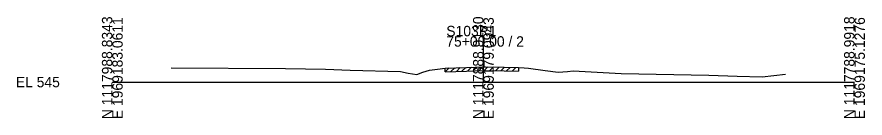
# Model space of a CAD drawing. Extents: x -26 to 203, y -10 to 12018.
# Drawn here: x -25.7 to 202.8, y 11490.3 to 11517.5 of the extents above; entities that cross this region are included whole.
import ezdxf

# ---------------------------------------------------------------- set-up
doc = ezdxf.new("R2010")
doc.units = 0
for name, color, linetype in [('Level 60', 7, 'Continuous'), ('Level 61', 7, 'Continuous'), ('Level 63', 7, 'Continuous')]:
    doc.layers.add(name, color=color, linetype=linetype)

msp = doc.modelspace()

# ---------------------------------------------------------------- linework, layer by layer
at = {"layer": 'Level 60'}
for p, q in [((15.83, 11503.81), (46.63, 11503.65)), ((46.63, 11503.65), (57.42, 11503.46)), ((57.42, 11503.46), (64.1, 11503.25)), ((64.1, 11503.25), (77.7, 11502.83)), ((77.7, 11502.83), (79.76, 11502.44)), ((79.76, 11502.44), (82.07, 11502.06)), ((82.07, 11502.06), (83.67, 11502.63)), ((83.67, 11502.63), (85.46, 11503.2)), ((85.46, 11503.2), (87.61, 11503.5)), ((87.61, 11503.5), (89.73, 11503.78)), ((89.73, 11503.78), (95.43, 11503.96)), ((95.43, 11503.96), (100, 11504.1)), ((100, 11504.1), (100.6, 11504.12)), ((100.6, 11504.12), (105.57, 11504)), ((105.57, 11504), (109.48, 11503.93)), ((109.48, 11503.93), (110.99, 11503.8)), ((110.99, 11503.8), (112.15, 11503.72)), ((112.15, 11503.72), (116.64, 11503.13)), ((116.64, 11503.13), (120.12, 11502.66)), ((120.12, 11502.66), (122.64, 11502.84)), ((122.64, 11502.84), (124.18, 11503)), ((124.18, 11503), (137.1, 11502.34)), ((137.1, 11502.34), (160.73, 11501.84)), ((175.09, 11501.43), (181.41, 11502.12)), ((160.73, 11501.84), (168.37, 11501.6)), ((168.37, 11501.6), (175.09, 11501.43))]:
    msp.add_line(p, q, dxfattribs=at)
at = {"layer": 'Level 61'}
for p, q in [((89.73, 11502.78), (90.77, 11503.81)), ((89.73, 11502.78), (89.73, 11503.78)), ((89.73, 11502.78), (95.43, 11502.96)), ((91.23, 11502.83), (92.27, 11503.86)), ((92.73, 11502.87), (93.77, 11503.91)), ((94.23, 11502.92), (95.27, 11503.95)), ((95.43, 11502.96), (100, 11503.1)), ((95.73, 11502.97), (96.77, 11504)), ((97.23, 11503.01), (98.27, 11504.04)), ((98.73, 11503.06), (99.77, 11504.09)), ((100, 11503.1), (100.6, 11503.12)), ((100.23, 11503.11), (101.23, 11504.1)), ((100.6, 11503.12), (105.57, 11503)), ((101.73, 11503.09), (102.71, 11504.07)), ((103.23, 11503.06), (104.21, 11504.03)), ((104.73, 11503.02), (105.71, 11504)), ((105.57, 11503), (109.48, 11502.93)), ((106.23, 11502.99), (107.22, 11503.97)), ((107.73, 11502.96), (108.72, 11503.94)), ((109.48, 11503.93), (109.48, 11502.93))]:
    msp.add_line(p, q, dxfattribs=at)
at = {"layer": 'Level 63'}
for p, q in [((100, 11500), (100, 11512.35)), ((0, 11500), (100, 11500)), ((100, 11500), (200, 11500))]:
    msp.add_line(p, q, dxfattribs=at)

# ---------------------------------------------------------------- texts
for s, p in [('N 1117988.8343', (0, 11490)), ('E 1969183.0611', (2.8, 11490)), ('N 1117888.9130', (100, 11490)), ('E 1969179.0943', (102.8, 11490)), ('N 1117788.9918', (200, 11490)), ('E 1969175.1276', (202.8, 11490))]:
    msp.add_text(s, height=2.8, rotation=90, dxfattribs=at).set_placement(p)
for s, p in [('S103R1', (90, 11512.35)), ('75+00.00 / 2', (90, 11509.55)), ('EL 545', (-26, 11498.6))]:
    msp.add_text(s, height=2.8, dxfattribs=at).set_placement(p)

doc.saveas('drawing.dxf')
